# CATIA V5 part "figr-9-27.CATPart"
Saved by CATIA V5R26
Part number: Part1
Bounding box of the stored display mesh (mm): x -75 to 75, y -50 to 50, z 0 to 40
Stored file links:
  D:\_Deepak\CATIA\CATIA V5-6R2016_Deepak\Resources\Part files\Partfiles\c09_catia_v5_6r2016_prt\figr-9-27.CATPart
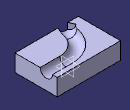
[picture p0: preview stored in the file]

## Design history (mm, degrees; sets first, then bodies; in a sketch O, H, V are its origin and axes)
Body1 (main body)
  Sketch1 on xy-plane, origin (0, 0, 0), H (1, 0, 0), V (0, 1, 0)
    line L1 (-75, 50) -> (75, 50)
    line L2 (75, 50) -> (75, -50)
    line L3 (75, -50) -> (-75, -50)
    line L4 (-75, -50) -> (-75, 50)
    axis line L5 (75, -50) -> (-75, 50)
    length L2 = 100
    length L3 = 150
    horizontal: L1 H, L3 H
    vertical: L2 V, L4 V
    midpoint: O L5
  Pad1: profile Sketch1, direction (0, 0, 1), length 40
  Sketch2 on face of Pad1, origin (75, 0, 0), H (0, 1, 0), V (0, 0, 1)
    arc A1 centre (24.1478, 40) radius 14.6047 from (9.543, 40) to (38.7525, 40) ccw
    point P1 (24.1478, 40)
    reference projected point E1 (24.1478, 40) from vertex of Sketch3
    line L1 (9.543, 40) -> (38.7525, 40)
    coincidence: P1 E1
    horizontal: L1 H
  Sketch3 on face of Pad1, origin (0, 0, 40), H (1, 0, 0), V (0, 1, 0)
    point P1 (75, 24.1478)
    line L1 (75, 24.1478) -> (28.6577, 24.1478)
    arc A1 centre (28.6577, -39.2062) radius 63.354 from (28.6577, 24.1478) to (-33.8383, -28.8149) ccw
    arc A2 centre (-62.192, -24.1005) radius 28.7429 from (-33.8383, -28.8149) to (-49.7271, -50) cw
    point P6 (-49.7271, -50)
    reference projected line E1 (75, -50) -> (75, 50) from edge [face of Pad1 | face of Pad1]
    reference projected line E2 (-75, -50) -> (75, -50) from edge [face of Pad1 | face of Pad1]
    horizontal: L1 H
    tangency: A1 L1, A2 A1
    coincidence: P1 E1, P6 E2
  Slot1: profile Sketch2, centre curve Sketch3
